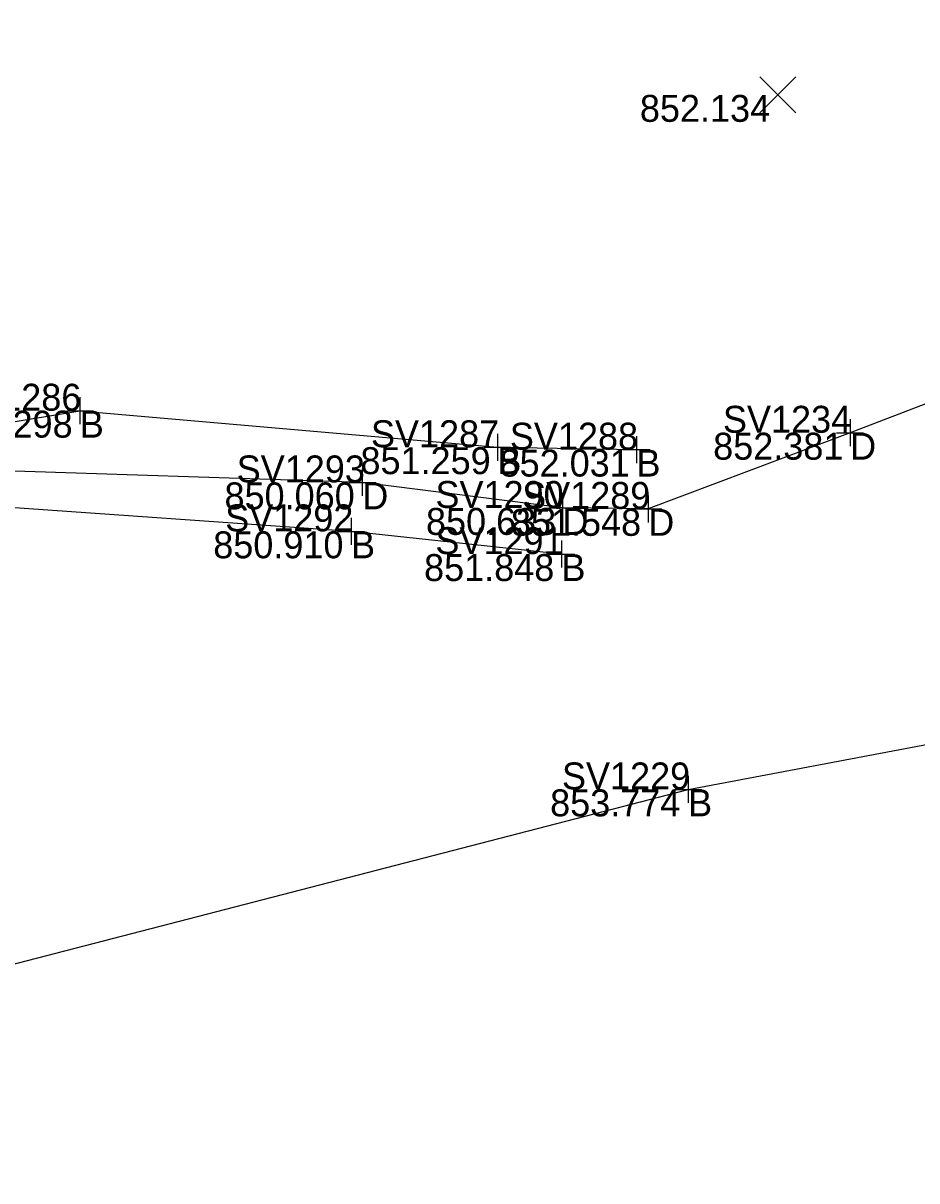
# Model space of a CAD drawing. Extents: x 2125299 to 2129212, y 713100 to 714300.
# Drawn here: x 2128322.56 to 2128355.73, y 714148.53 to 714191.52 of the extents above; entities that cross this region are included whole.
import ezdxf

# ---------------------------------------------------------------- set-up
doc = ezdxf.new("R2010")
doc.units = 0
for name, color, linetype in [('DR_X_Ditch', 7, 'Continuous'), ('RW_P_Esmt_TMP', 7, 'Continuous'), ('RW_X_Esmt_CH', 7, 'Continuous'), ('RW_X_Fee_WL', 7, 'Continuous'), ('SV_X_Break_Lines', 7, 'Continuous'), ('SV_X_Mon_Cells_Found', 7, 'Continuous'), ('SV_X_Text_Elevation', 7, 'Continuous')]:
    doc.layers.add(name, color=color, linetype=linetype)

msp = doc.modelspace()

# ---------------------------------------------------------------- linework, layer by layer
at = {"layer": 'DR_X_Ditch'}
msp.add_lwpolyline([(2128404.428, 714186.272), (2128369.06, 714182.378), (2128353.253, 714176.31), (2128345.761, 714173.482), (2128342.574, 714173.517), (2128335.146, 714174.466), (2128320.718, 714174.933), (2128310.69, 714174.47), (2128298.547, 714171.487), (2128292.157, 714172.437), (2128287.299, 714171.899), (2128282.282, 714171.907)], dxfattribs=at)
at = {"layer": 'SV_X_Break_Lines'}
msp.add_line((2128342.539, 714171.803), (2128342.539, 714171.803), dxfattribs=at)
for points in [[(2128294.731, 714221.25), (2128286.429, 714216.107), (2128286.307, 714216.085), (2128290.211, 714206.434), (2128289.886, 714198.061), (2128291.79, 714193.305), (2128293.753, 714188.829), (2128301.414, 714189.738), (2128311.099, 714187.98), (2128315.392, 714186.993), (2128315.738, 714184.367), (2128308.586, 714184.286), (2128301.154, 714185.129), (2128295.038, 714185.419), (2128293.414, 714179.277), (2128290.994, 714176.583), (2128286.414, 714175.49), (2128286.417, 714175.493), (2128286.617, 714173.173), (2128291.92, 714175.499), (2128298.034, 714172.742), (2128324.661, 714177.129), (2128340.162, 714175.773), (2128345.323, 714175.683)], [(2128257.59, 714155.557), (2128263.487, 714153.243), (2128269.265, 714148.527), (2128290.131, 714150.799), (2128296.994, 714153.375), (2128311.857, 714153.897), (2128347.24, 714163.065), (2128380.908, 714169.426), (2128405.403, 714183.348)], [(2128342.539, 714171.803), (2128334.728, 714172.648), (2128320.995, 714173.612), (2128310.963, 714173.215), (2128298.394, 714170.12), (2128293.384, 714169.367), (2128288.065, 714167.811), (2128285.175, 714167.243), (2128284.357, 714164.829), (2128284.794, 714163.766)]]:
    msp.add_lwpolyline(points, dxfattribs=at)
at = {"layer": 'SV_X_Mon_Cells_Found'}
for p, q in [((2128324.661, 714177.629), (2128324.661, 714176.629)), ((2128324.161, 714177.129), (2128325.161, 714177.129)), ((2128324.661, 714177.129), (2128324.661, 714177.129)), ((2128353.253, 714176.81), (2128353.253, 714175.81)), ((2128352.753, 714176.31), (2128353.753, 714176.31)), ((2128353.253, 714176.31), (2128353.253, 714176.31)), ((2128340.162, 714176.273), (2128340.162, 714175.273)), ((2128345.323, 714176.183), (2128345.323, 714175.183)), ((2128339.662, 714175.773), (2128340.662, 714175.773)), ((2128340.162, 714175.773), (2128340.162, 714175.773)), ((2128344.823, 714175.683), (2128345.823, 714175.683)), ((2128345.323, 714175.683), (2128345.323, 714175.683)), ((2128335.146, 714174.966), (2128335.146, 714173.966)), ((2128334.646, 714174.466), (2128335.646, 714174.466)), ((2128335.146, 714174.466), (2128335.146, 714174.466)), ((2128342.574, 714174.017), (2128342.574, 714173.017)), ((2128345.761, 714173.982), (2128345.761, 714172.982)), ((2128342.074, 714173.517), (2128343.074, 714173.517)), ((2128342.574, 714173.517), (2128342.574, 714173.517)), ((2128345.261, 714173.482), (2128346.261, 714173.482)), ((2128345.761, 714173.482), (2128345.761, 714173.482)), ((2128334.728, 714173.148), (2128334.728, 714172.148)), ((2128334.228, 714172.648), (2128335.228, 714172.648)), ((2128334.728, 714172.648), (2128334.728, 714172.648)), ((2128342.539, 714172.303), (2128342.539, 714171.303)), ((2128342.039, 714171.803), (2128343.039, 714171.803)), ((2128342.539, 714171.803), (2128342.539, 714171.803)), ((2128347.24, 714163.565), (2128347.24, 714162.565)), ((2128346.74, 714163.065), (2128347.74, 714163.065)), ((2128347.24, 714163.065), (2128347.24, 714163.065))]:
    msp.add_line(p, q, dxfattribs=at)
at = {"layer": 'SV_X_Text_Elevation'}
for p, q in [((2128349.905, 714188.19), (2128351.239, 714189.525)), ((2128349.905, 714189.525), (2128351.239, 714188.19))]:
    msp.add_line(p, q, dxfattribs=at)

# ---------------------------------------------------------------- texts
at = {"layer": 'RW_P_Esmt_TMP'}
for s, p in [('B', (2128324.661, 714176.129)), ('D', (2128353.253, 714175.31)), ('B', (2128340.162, 714174.773)), ('B', (2128345.323, 714174.683)), ('D', (2128335.146, 714173.466)), ('D', (2128342.574, 714172.517)), ('D', (2128345.761, 714172.482)), ('B', (2128334.728, 714171.648)), ('B', (2128342.539, 714170.803)), ('B', (2128347.24, 714162.065))]:
    msp.add_text(s, height=1, dxfattribs=at).set_placement(p)
at = {"layer": 'RW_X_Esmt_CH'}
for s, p in [('SV1286', (2128319.959, 714177.129)), ('SV1234', (2128348.533, 714176.31)), ('SV1287', (2128335.468, 714175.773)), ('SV1288', (2128340.624, 714175.683)), ('SV1293', (2128330.484, 714174.466)), ('SV1290', (2128337.862, 714173.517)), ('SV1289', (2128341.079, 714173.482)), ('SV1292', (2128330.057, 714172.648)), ('SV1291', (2128337.859, 714171.803)), ('SV1229', (2128342.558, 714163.065))]:
    msp.add_text(s, height=1, dxfattribs=at).set_placement(p)
at = {"layer": 'RW_X_Fee_WL'}
for s, p in [('852.134', (2128345.45, 714187.857)), ('850.298', (2128319.561, 714176.129)), ('852.381', (2128348.171, 714175.31)), ('851.259', (2128335.078, 714174.773)), ('852.031', (2128340.241, 714174.683)), ('850.060', (2128330.032, 714173.466)), ('850.633', (2128337.51, 714172.517)), ('851.548', (2128340.661, 714172.482)), ('850.910', (2128329.614, 714171.648)), ('851.848', (2128337.439, 714170.803)), ('853.774', (2128342.118, 714162.065))]:
    msp.add_text(s, height=1, dxfattribs=at).set_placement(p)

doc.saveas('drawing.dxf')
